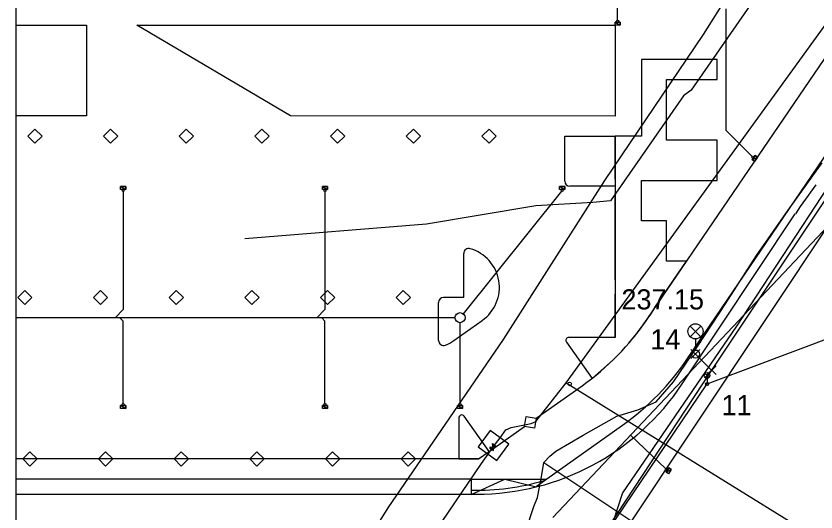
# Model space of a CAD drawing. Extents: x -263861 to -263441, y -1242367 to -1242070.
# Drawn here: x -263861.4 to -263782.2, y -1242303.2 to -1242254.1 of the extents above; entities that cross this region are included whole.
import ezdxf

# ---------------------------------------------------------------- set-up
doc = ezdxf.new("R2010")
doc.units = 0
for name, color, linetype in [('KFA_BODY', 7, 'Continuous'), ('KFA_JESTV_IS_DSP', 7, 'Continuous'), ('KFA_SITUACIA_DSP', 7, 'Continuous'), ('KFA_VO_prelozka_pri_vjazde_do KFA_LAMPA', 7, 'Continuous'), ('KFA_VO_prelozka_pri_vjazde_do KFA_TRASA', 7, 'Continuous'), ('RAM_NA_TLAC_A3_1-1000', 7, 'Continuous')]:
    doc.layers.add(name, color=color, linetype=linetype)

msp = doc.modelspace()

# ---------------------------------------------------------------- linework, layer by layer
at = {"layer": 'KFA_BODY'}
for p, q in [((-263794.554, -1242288.029), (-263793.67, -1242287.145)), ((-263793.67, -1242288.029), (-263794.554, -1242287.145)), ((-263794.112, -1242287.587), (-263794.112, -1242287.587)), ((-263792.955, -1242289.628), (-263792.071, -1242288.744)), ((-263792.071, -1242289.628), (-263792.955, -1242288.744)), ((-263792.513, -1242289.186), (-263792.513, -1242289.186))]:
    msp.add_line(p, q, dxfattribs=at)
at = {"layer": 'KFA_JESTV_IS_DSP'}
for p, q in [((-263806.91, -1242290.428), (-263750, -1242211.711)), ((-263793.322, -1242255.892), (-263787.303, -1242246.375)), ((-263787.86, -1242251.774), (-263794.538, -1242261.421)), ((-263803.105, -1242270.385), (-263793.322, -1242255.892)), ((-263794.538, -1242261.421), (-263795.294, -1242261.994)), ((-263795.294, -1242261.994), (-263802.528, -1242272.409)), ((-263784.91, -1242273.31), (-263781.56, -1242268.62)), ((-263813.147, -1242286.151), (-263803.105, -1242270.385)), ((-263780.3, -1242269.92), (-263790.03, -1242284.82)), ((-263804.296, -1242272.568), (-263809.931, -1242272.893)), ((-263802.528, -1242272.409), (-263804.296, -1242272.568)), ((-263809.931, -1242272.893), (-263820.768, -1242274.703)), ((-263788.05, -1242277.83), (-263784.91, -1242273.31)), ((-263820.768, -1242274.703), (-263838.767, -1242276.172)), ((-263791.14, -1242282.61), (-263788.05, -1242277.83)), ((-263792.966, -1242290.553), (-263765.274, -1242280.104)), ((-263793.85, -1242286.75), (-263791.14, -1242282.61)), ((-263790.03, -1242284.82), (-263801.33, -1242301.36)), ((-263824.576, -1242302.847), (-263813.147, -1242286.151)), ((-263796.3, -1242290.34), (-263793.85, -1242286.75)), ((-263793.165, -1242289.511), (-263792.767, -1242289.908)), ((-263792.767, -1242289.511), (-263793.165, -1242289.908)), ((-263792.966, -1242289.991), (-263792.966, -1242290.553)), ((-263817.295, -1242326.595), (-263792.966, -1242290.553)), ((-263809.913, -1242294.27), (-263806.91, -1242290.428)), ((-263806.91, -1242290.428), (-263775.785, -1242309.71)), ((-263798, -1242292.34), (-263796.3, -1242290.34)), ((-263799.83, -1242293.13), (-263798, -1242292.34)), ((-263801.89, -1242293.76), (-263799.83, -1242293.13)), ((-263805.23, -1242295.63), (-263801.89, -1242293.76)), ((-263812.89, -1242295.097), (-263812.358, -1242294.872)), ((-263812.358, -1242294.872), (-263810.39, -1242294.475)), ((-263810.39, -1242294.475), (-263809.913, -1242294.27)), ((-263814.453, -1242295.177), (-263815.644, -1242296.782)), ((-263812.615, -1242296.506), (-263814.453, -1242295.177)), ((-263813.466, -1242295.89), (-263812.89, -1242295.097)), ((-263807.96, -1242297.22), (-263805.23, -1242295.63)), ((-263814.214, -1242296.439), (-263813.813, -1242296.738)), ((-263814.112, -1242297.139), (-263814.214, -1242296.439)), ((-263814.163, -1242296.789), (-263813.466, -1242295.89)), ((-263813.787, -1242298.143), (-263812.615, -1242296.506)), ((-263815.644, -1242296.782), (-263813.787, -1242298.143)), ((-263815.644, -1242296.782), (-263815.644, -1242296.782)), ((-263814.667, -1242297.5), (-263814.163, -1242296.789)), ((-263813.813, -1242296.738), (-263814.513, -1242296.84)), ((-263814.513, -1242296.84), (-263814.112, -1242297.139)), ((-263808.54, -1242297.7), (-263807.96, -1242297.22)), ((-263815.315, -1242298.423), (-263814.667, -1242297.5)), ((-263809.14, -1242298.34), (-263808.54, -1242297.7)), ((-263826.85, -1242315.4), (-263815.315, -1242298.423)), ((-263809.38, -1242299.75), (-263809.14, -1242298.34)), ((-263809.14, -1242298.34), (-263799.44, -1242304.8)), ((-263809.78, -1242301.82), (-263809.38, -1242299.75)), ((-263810.13, -1242302.69), (-263809.78, -1242301.82)), ((-263801.33, -1242301.36), (-263802.26, -1242304.18)), ((-263831.753, -1242314.378), (-263824.576, -1242302.847)), ((-263811.16, -1242305.78), (-263810.13, -1242302.69))]:
    msp.add_line(p, q, dxfattribs=at)
for centre, radius in [((-263792.966, -1242289.709), 0.281), ((-263806.579, -1242290.547), 0.179), ((-263792.966, -1242290.553), 0.15)]:
    msp.add_circle(centre, radius, dxfattribs=at)
at = {"layer": 'KFA_SITUACIA_DSP'}
for p, q in [((-263822.88, -1242337.914), (-263734.49, -1242204.937)), ((-263794.898, -1242288.032), (-263742.736, -1242211.145)), ((-263798.899, -1242284.125), (-263751.864, -1242215.081)), ((-263801.822, -1242254.497), (-263801.837, -1242252.972)), ((-263791.063, -1242265.427), (-263791.063, -1242253.362)), ((-263802.071, -1242254.697), (-263801.571, -1242254.697)), ((-263802.071, -1242254.987), (-263802.071, -1242254.697)), ((-263802.071, -1242254.697), (-263801.571, -1242254.987)), ((-263802.071, -1242254.697), (-263801.571, -1242254.987)), ((-263801.571, -1242254.697), (-263802.071, -1242254.697)), ((-263801.571, -1242254.987), (-263802.071, -1242254.987)), ((-263801.571, -1242254.697), (-263801.571, -1242254.987)), ((-263801.571, -1242254.987), (-263801.571, -1242254.697)), ((-263788.502, -1242267.989), (-263791.063, -1242265.427)), ((-263807.068, -1242270.447), (-263807.068, -1242265.987)), ((-263807.068, -1242265.987), (-263802.068, -1242265.987)), ((-263802.068, -1242270.24), (-263802.068, -1242265.987)), ((-263788.491, -1242268.322), (-263788.207, -1242267.91)), ((-263788.207, -1242267.91), (-263788.491, -1242268.322)), ((-263788.207, -1242267.91), (-263787.968, -1242268.075)), ((-263787.968, -1242268.075), (-263788.207, -1242267.91)), ((-263788.491, -1242268.322), (-263787.968, -1242268.075)), ((-263788.491, -1242268.322), (-263787.968, -1242268.075)), ((-263788.252, -1242268.487), (-263788.491, -1242268.322)), ((-263787.968, -1242268.075), (-263788.252, -1242268.487)), ((-263851.074, -1242270.983), (-263850.574, -1242270.983)), ((-263851.074, -1242271.273), (-263851.074, -1242270.983)), ((-263851.074, -1242270.983), (-263850.574, -1242271.273)), ((-263851.074, -1242270.983), (-263850.574, -1242271.273)), ((-263850.574, -1242270.983), (-263851.074, -1242270.983)), ((-263850.574, -1242270.983), (-263850.574, -1242271.273)), ((-263850.574, -1242271.273), (-263850.574, -1242270.983)), ((-263831.074, -1242270.983), (-263830.574, -1242270.983)), ((-263831.074, -1242271.273), (-263831.074, -1242270.983)), ((-263831.074, -1242270.983), (-263830.574, -1242271.273)), ((-263831.074, -1242270.983), (-263830.574, -1242271.273)), ((-263830.574, -1242270.983), (-263831.074, -1242270.983)), ((-263830.574, -1242270.983), (-263830.574, -1242271.273)), ((-263830.574, -1242271.273), (-263830.574, -1242270.983)), ((-263807.568, -1242270.982), (-263807.068, -1242270.982)), ((-263807.568, -1242271.272), (-263807.568, -1242270.982)), ((-263807.568, -1242270.982), (-263807.068, -1242271.272)), ((-263807.568, -1242270.982), (-263807.068, -1242271.272)), ((-263807.068, -1242270.982), (-263807.568, -1242270.982)), ((-263807.068, -1242270.982), (-263807.068, -1242271.272)), ((-263807.068, -1242271.272), (-263807.068, -1242270.982)), ((-263802.068, -1242270.947), (-263806.568, -1242270.947)), ((-263850.574, -1242271.273), (-263851.074, -1242271.273)), ((-263850.824, -1242271.473), (-263850.824, -1242283.187)), ((-263830.574, -1242271.273), (-263831.074, -1242271.273)), ((-263830.824, -1242271.473), (-263830.824, -1242283.187)), ((-263807.38, -1242271.45), (-263817.128, -1242283.593)), ((-263807.068, -1242271.272), (-263807.568, -1242271.272)), ((-263802.068, -1242280.24), (-263802.068, -1242271.654)), ((-263780.353, -1242274.236), (-263808.248, -1242303.783)), ((-263795.416, -1242290.541), (-263784.214, -1242273.68)), ((-263817.068, -1242281.982), (-263817.068, -1242277.62)), ((-263817.068, -1242281.982), (-263819.068, -1242281.982)), ((-263802.068, -1242285.947), (-263802.068, -1242281.654)), ((-263819.568, -1242286.231), (-263819.568, -1242282.482)), ((-263850.824, -1242283.187), (-263851.619, -1242283.982)), ((-263830.824, -1242283.187), (-263831.619, -1242283.982)), ((-263817.941, -1242283.982), (-263861.443, -1242283.982)), ((-263817.941, -1242283.982), (-263861.443, -1242283.982)), ((-263850.824, -1242284.343), (-263851.149, -1242283.982)), ((-263850.824, -1242292.492), (-263850.824, -1242284.343)), ((-263830.824, -1242284.343), (-263831.149, -1242283.982)), ((-263830.824, -1242292.492), (-263830.824, -1242284.343)), ((-263818.06, -1242286.248), (-263815.232, -1242284.248)), ((-263817.441, -1242292.492), (-263817.441, -1242284.482)), ((-263809.895, -1242293.947), (-263805.344, -1242290.728)), ((-263851.074, -1242292.693), (-263850.574, -1242292.693)), ((-263851.074, -1242292.983), (-263851.074, -1242292.693)), ((-263851.074, -1242292.693), (-263850.574, -1242292.983)), ((-263851.074, -1242292.693), (-263850.574, -1242292.983)), ((-263850.574, -1242292.693), (-263851.074, -1242292.693)), ((-263850.574, -1242292.983), (-263851.074, -1242292.983)), ((-263850.574, -1242292.693), (-263850.574, -1242292.983)), ((-263850.574, -1242292.983), (-263850.574, -1242292.693)), ((-263831.074, -1242292.693), (-263830.574, -1242292.693)), ((-263831.074, -1242292.983), (-263831.074, -1242292.693)), ((-263831.074, -1242292.693), (-263830.574, -1242292.983)), ((-263831.074, -1242292.693), (-263830.574, -1242292.983)), ((-263830.574, -1242292.693), (-263831.074, -1242292.693)), ((-263830.574, -1242292.983), (-263831.074, -1242292.983)), ((-263830.824, -1242292.693), (-263830.824, -1242292.692)), ((-263830.574, -1242292.693), (-263830.574, -1242292.983)), ((-263830.574, -1242292.983), (-263830.574, -1242292.693)), ((-263817.691, -1242292.692), (-263817.191, -1242292.692)), ((-263817.691, -1242292.982), (-263817.691, -1242292.692)), ((-263817.691, -1242292.692), (-263817.191, -1242292.982)), ((-263817.691, -1242292.692), (-263817.191, -1242292.982)), ((-263817.191, -1242292.692), (-263817.691, -1242292.692)), ((-263817.191, -1242292.982), (-263817.691, -1242292.982)), ((-263817.191, -1242292.692), (-263817.191, -1242292.982)), ((-263817.191, -1242292.982), (-263817.191, -1242292.692)), ((-263814.555, -1242297.242), (-263811.05, -1242294.763)), ((-263809.875, -1242300.669), (-263801.342, -1242294.634)), ((-263797.048, -1242298.952), (-263800.558, -1242295.638)), ((-263815.601, -1242297.982), (-263861.443, -1242297.982)), ((-263797.029, -1242299.286), (-263796.75, -1242298.871)), ((-263796.75, -1242298.871), (-263797.029, -1242299.286)), ((-263796.75, -1242298.871), (-263796.51, -1242299.032)), ((-263796.51, -1242299.032), (-263796.75, -1242298.871)), ((-263797.029, -1242299.286), (-263796.51, -1242299.032)), ((-263797.029, -1242299.286), (-263796.51, -1242299.032)), ((-263796.788, -1242299.448), (-263797.029, -1242299.286)), ((-263796.51, -1242299.032), (-263796.788, -1242299.448)), ((-263816.308, -1242299.982), (-263861.443, -1242299.982)), ((-263816.308, -1242301.482), (-263816.308, -1242299.982)), ((-263816.308, -1242299.982), (-263808.904, -1242299.982)), ((-263809.906, -1242300.757), (-263809.875, -1242300.669)), ((-263861.443, -1242301.482), (-263815.822, -1242301.482))]:
    msp.add_line(p, q, dxfattribs=at)
for points in [[(-263861.443, -1242254.984), (-263854.468, -1242254.985), (-263854.468, -1242263.985)], [(-263798.064, -1242282.882), (-263794.987, -1242278.383), (-263796.968, -1242278.382), (-263796.968, -1242274.382), (-263799.468, -1242274.382), (-263799.468, -1242270.382), (-263791.968, -1242270.382), (-263791.968, -1242266.382), (-263796.968, -1242266.382), (-263796.968, -1242260.382), (-263791.968, -1242260.382), (-263791.968, -1242258.382), (-263799.468, -1242258.382), (-263799.468, -1242265.987), (-263802.068, -1242265.987)], [(-263854.468, -1242263.985), (-263861.443, -1242263.984)], [(-263802.068, -1242265.987), (-263802.068, -1242270.24), (-263802.068, -1242270.947), (-263802.068, -1242271.654), (-263802.068, -1242273.447), (-263802.068, -1242275.947), (-263802.068, -1242278.447), (-263802.068, -1242280.24), (-263802.068, -1242280.24), (-263802.068, -1242281.654), (-263802.068, -1242283.447), (-263802.068, -1242285.947), (-263806.656, -1242285.943)], [(-263806.901, -1242286.416), (-263804.349, -1242290.024), (-263802.552, -1242288.44)], [(-263817.568, -1242293.926), (-263817.568, -1242297.982), (-263815.601, -1242297.982), (-263814.555, -1242297.242), (-263817.023, -1242293.753)], [(-263816.327, -1242301.51), (-263813.002, -1242299.982), (-263809.906, -1242300.757)]]:
    msp.add_lwpolyline(points, dxfattribs=at)
for points in [[(-263802.068, -1242263.988), (-263834.256, -1242263.984), (-263849.468, -1242254.985), (-263802.068, -1242254.987)], [(-263859.568, -1242265.279), (-263858.861, -1242265.986), (-263859.568, -1242266.693), (-263860.275, -1242265.986)], [(-263852.068, -1242265.279), (-263851.361, -1242265.986), (-263852.068, -1242266.693), (-263852.775, -1242265.986)], [(-263844.568, -1242265.279), (-263843.861, -1242265.986), (-263844.568, -1242266.693), (-263845.275, -1242265.986)], [(-263837.068, -1242265.279), (-263836.361, -1242265.986), (-263837.068, -1242266.693), (-263837.775, -1242265.986)], [(-263829.568, -1242265.279), (-263828.861, -1242265.986), (-263829.568, -1242266.693), (-263830.275, -1242265.986)], [(-263822.068, -1242265.279), (-263821.361, -1242265.986), (-263822.068, -1242266.694), (-263822.775, -1242265.986)], [(-263814.568, -1242265.279), (-263813.861, -1242265.986), (-263814.568, -1242266.693), (-263815.275, -1242265.986)], [(-263860.568, -1242281.275), (-263859.861, -1242281.982), (-263860.568, -1242282.689), (-263861.275, -1242281.982)], [(-263853.068, -1242281.275), (-263852.361, -1242281.982), (-263853.068, -1242282.689), (-263853.775, -1242281.982)], [(-263845.568, -1242281.275), (-263844.861, -1242281.982), (-263845.568, -1242282.689), (-263846.275, -1242281.982)], [(-263838.068, -1242281.275), (-263837.361, -1242281.982), (-263838.068, -1242282.689), (-263838.775, -1242281.982)], [(-263830.568, -1242281.275), (-263829.861, -1242281.982), (-263830.568, -1242282.689), (-263831.275, -1242281.982)], [(-263823.068, -1242281.275), (-263822.361, -1242281.982), (-263823.068, -1242282.689), (-263823.775, -1242281.982)], [(-263810.881, -1242293.778), (-263809.895, -1242293.947), (-263810.064, -1242294.932), (-263811.05, -1242294.763)], [(-263860.068, -1242297.275), (-263859.361, -1242297.982), (-263860.068, -1242298.689), (-263860.775, -1242297.982)], [(-263852.568, -1242297.275), (-263851.861, -1242297.982), (-263852.568, -1242298.689), (-263853.275, -1242297.982)], [(-263845.068, -1242297.275), (-263844.361, -1242297.982), (-263845.068, -1242298.689), (-263845.775, -1242297.982)], [(-263837.568, -1242297.275), (-263836.861, -1242297.982), (-263837.568, -1242298.689), (-263838.275, -1242297.982)], [(-263830.068, -1242297.275), (-263829.361, -1242297.982), (-263830.068, -1242298.689), (-263830.775, -1242297.982)], [(-263822.568, -1242297.275), (-263821.861, -1242297.982), (-263822.568, -1242298.689), (-263823.275, -1242297.982)]]:
    msp.add_lwpolyline(points, close=True, dxfattribs=at)
for centre, radius in [((-263801.821, -1242254.597), 0.1), ((-263788.431, -1242268.059), 0.1), ((-263850.824, -1242271.373), 0.1), ((-263830.824, -1242271.373), 0.1), ((-263807.318, -1242271.372), 0.1), ((-263817.441, -1242283.982), 0.5), ((-263850.824, -1242292.592), 0.1), ((-263830.824, -1242292.592), 0.1), ((-263817.441, -1242292.592), 0.1), ((-263796.975, -1242299.02), 0.1)]:
    msp.add_circle(centre, radius, dxfattribs=at)
for centre, radius, start, end in [((-263806.568, -1242270.447), 0.5, 180, 270), ((-263742.568, -1242301.35), 50, 142.36875, 146.39918), ((-263816.568, -1242277.62), 0.5, 73.84458, 180), ((-263817.542, -1242280.982), 4, 305.27024, 73.84458), ((-263819.068, -1242282.482), 0.5, 90, 180), ((-263821.806, -1242268.304), 27.86, 313.71918, 328.45017), ((-263820.069, -1242269.909), 25.5, 305.27024, 326.11647), ((-263819.068, -1242286.231), 0.5, 180, 291.83316), ((-263820.369, -1242282.982), 4, 291.83316, 305.27024), ((-263806.656, -1242286.243), 0.3, 89.94357, 215.27024), ((-263816.067, -1242273.815), 25.5, 305.27024, 326.11647), ((-263815.822, -1242276.982), 24.5, 270, 326.39918), ((-263817.268, -1242293.926), 0.3, 35.27024, 180), ((-263815.836, -1242276.967), 24.119, 268.87866, 286.17976)]:
    msp.add_arc(centre, radius, start, end, dxfattribs=at)
at = {"layer": 'KFA_VO_prelozka_pri_vjazde_do KFA_LAMPA'}
for p, q in [((-263794.642, -1242285.867), (-263793.582, -1242284.807)), ((-263794.642, -1242284.807), (-263793.582, -1242285.867)), ((-263794.112, -1242286.087), (-263794.112, -1242287.187))]:
    msp.add_line(p, q, dxfattribs=at)
for centre, radius in [((-263794.112, -1242285.337), 0.75), ((-263794.112, -1242287.587), 0.4)]:
    msp.add_circle(centre, radius, dxfattribs=at)
at = {"layer": 'KFA_VO_prelozka_pri_vjazde_do KFA_TRASA'}
msp.add_line((-263794.112, -1242287.587), (-263792.513, -1242289.186), dxfattribs=at)
msp.add_lwpolyline([(-263678.348, -1242101.421), (-263696.564, -1242141.184), (-263711.214, -1242160.531), (-263718.885, -1242173.716), (-263725.972, -1242184.27), (-263742.987, -1242211.896), (-263755.733, -1242230.932), (-263756.364, -1242233.146), (-263759.746, -1242241.517), (-263769.698, -1242254.926), (-263792.513, -1242289.186), (-263819.793, -1242330.655), (-263820.536, -1242331.859)], dxfattribs=at)
at = {"layer": 'RAM_NA_TLAC_A3_1-1000'}
msp.add_lwpolyline([(-263861.443, -1242070.205), (-263441.443, -1242070.205), (-263441.443, -1242367.205), (-263861.443, -1242367.205)], close=True, dxfattribs=at)

# ---------------------------------------------------------------- texts
at = {"layer": 'KFA_BODY'}
for s, p in [('237.15', (-263801.444, -1242283.166)), ('14', (-263798.582, -1242287.122)), ('11', (-263791.528, -1242293.647))]:
    msp.add_text(s, height=2, dxfattribs=at).set_placement(p)

doc.saveas('drawing.dxf')
